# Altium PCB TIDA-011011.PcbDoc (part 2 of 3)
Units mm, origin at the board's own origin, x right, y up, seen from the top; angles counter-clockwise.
Board outline 61 x 47.5 mm, 4 copper layers (Top Layer, Layer 1, Layer 2, Bottom Layer), stack 1.787 mm thick; 171 components, 73 nets, 455 pads, 298 vias.
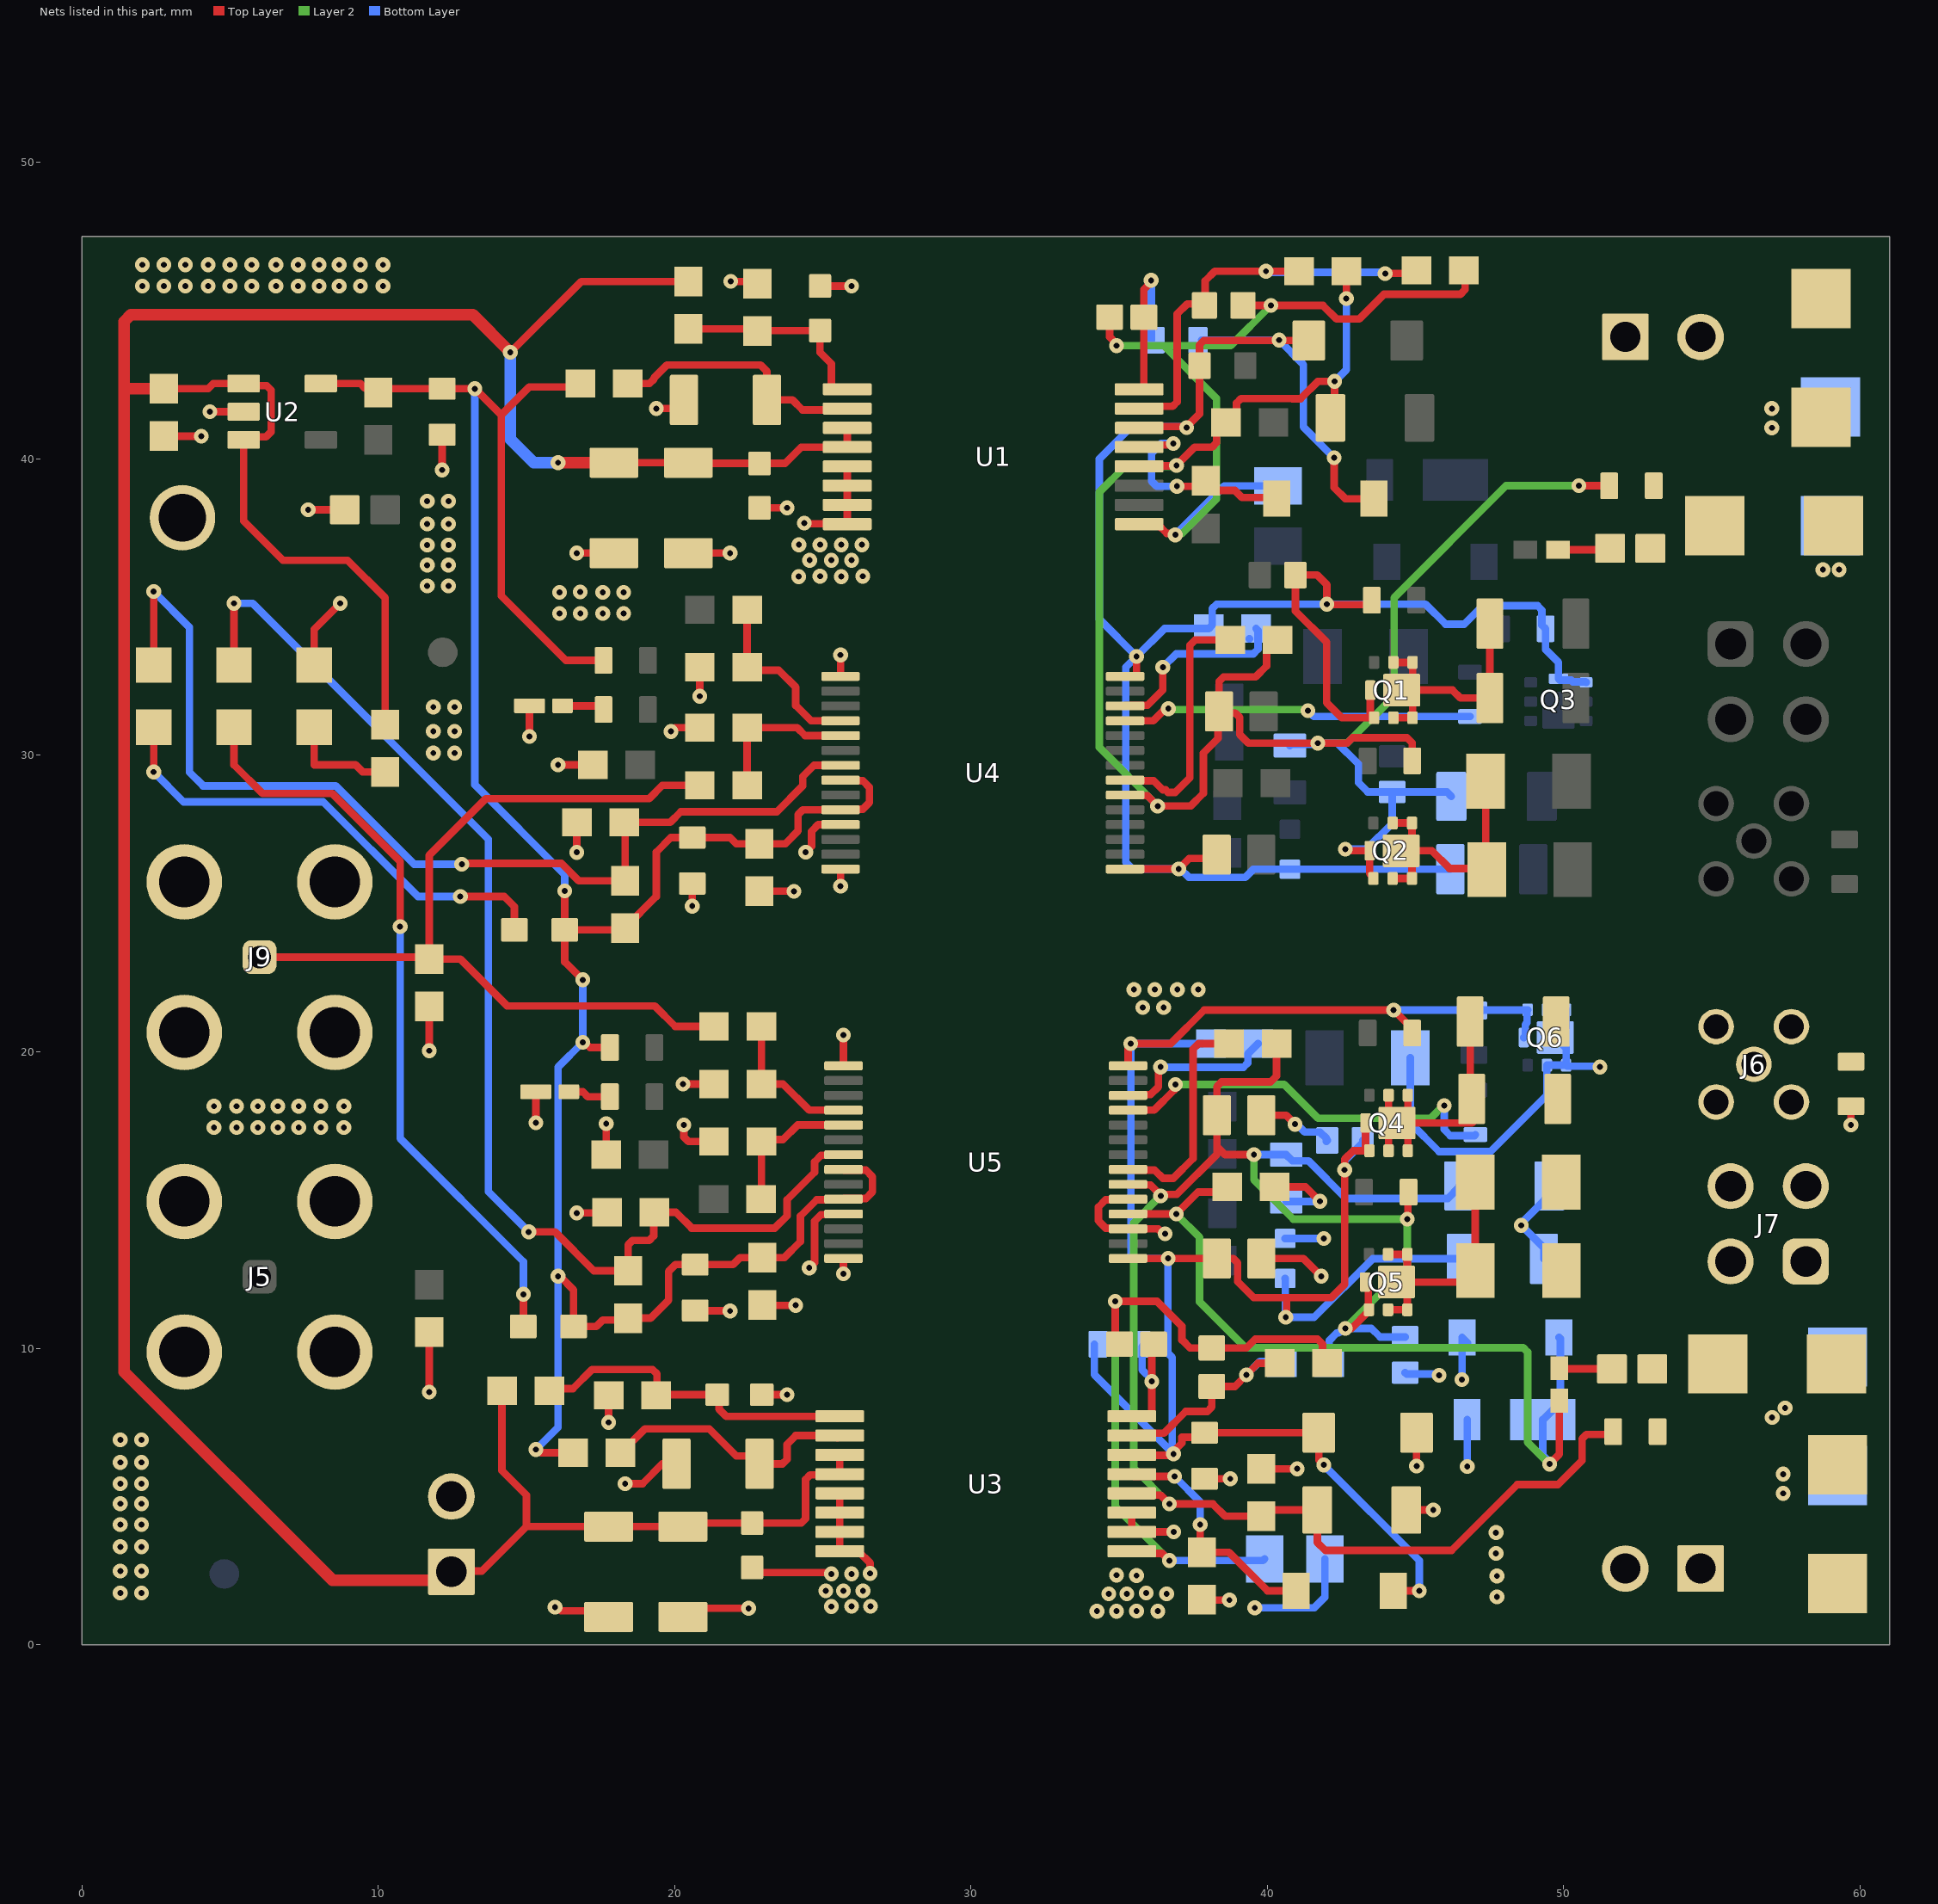
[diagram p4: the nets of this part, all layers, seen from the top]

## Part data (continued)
C40 C53: library part CMP-0122429-1, "1 µF ±10% 16V Ceramic Capacitor X7S 0603 (1608 Metric)", Digikey Part Number=490-GRM188C71C105KA12DTR-ND, Manufacturer=Murata, Mouser Part Number=81-GRM188C71C105KA2D, Operating Temperature Range="-55°C to +125°C", TempCo=22%, Temperature Characteristic=X7S, Tolerance_%=10%, ValueDisplayed=1uF
C41 C54: library part CMP-0006751-4, "CAP, CERM, 100 pF, 25 V, +/- 10%, X7R, 0603", Cap_Case=0603, Manufacturer=AVX, Supplier Part Number 1=55J3899, TempCo=X7R, Tolerance_%=10%, Value1=Unknown, Value2=25V, ValueDisplayed=100pF
C55 C56 C57 C58: library part CMP-0093594-1, "0.1 µF ±10% 50V Ceramic Capacitor X7R 0603 (1608 Metric)", Digikey Part Number=399-C0603C104K5RAC3121TR-ND, Manufacturer=KEMET, Mouser Part Number=80-C603C104K5RAC3121, Operating Temperature Range="-55°C to +125°C", TempCo=15%, Temperature Characteristic=X7R, Tolerance_%=10%, ValueDisplayed=0.1uF
D1 D2: library part CMP-0028628-2, "Diode, Schottky, 40 V, 2 A, SOD-123", Manufacturer=Rohm, Value1=2A, Value2=0.56V
D3 D4 D5: library part CMP-0002983-3, "LED, Red, SMD", Color=red, Manufacturer=OSRAM, Value1=W, Value2=1.8V
D6 D7: library part CMP-0093310-1, "Standard LEDs - SMD Green TOPLED E 1608", Color=Green, Forward Current=2mA, Manufacturer="Osram Opto", Mouser Part Number=720-KGDELLS122A4849, Operating Temperature Range="-40°C to +110°C"
D8 D9 D13 D14 D18 D19: library part CMP-0077081-2, "Diode, Ultrafast, 1200 V, 1 A, SMA", Manufacturer=STMicroelectronics, Value1=1A, Value2=1.9V
D10 D15: library part CMP-0005892-4, "Diode, Zener, 2.7 V, 300 mW, SOD-523", Manufacturer="Diodes Inc.", Power_W=300mW, Value1=0.3W
D11 D16: library part CMP-0077574-3, "Diode, Zener, 14 V, 500 mW, AEC-Q101, SOD-123", Manufacturer=Vishay-Semiconductor, Power_W=500mW, Value1=0.5W
D12 D17: library part CMP-0005417-4, "Diode, Zener, 30 V, 1 W, PowerDI123", Manufacturer="Diodes Inc.", Power_W=1W
FID1 FID2: library part CMP-0077181-1, "Fiducial mark.  There is nothing to buy or mount.", Manufacturer=N/A
J1 J4 J8: library part CMP-0092582-1, "KK 254 Breakaway Header, Right-Angle with Friction Lock, 2 Circuits, Tin (Sn) Plating", Current_A=4A, Digikey Part Number=WM19485-ND, Manufacturer=Molex, Mouser Part Number=538-22-28-1020, Operating Temperature Range=to, Voltage_V=500V
J2 J6: library part CMP-0075554-1, "Connector, MMCX 50 ohm, TH", Manufacturer=Samtec, Supplier Part Number 1=88K0549
J3 J7: library part CMP-0055713-1, "Receptacle, 2.54mm, 2x2, Gold, TH", Color=Black, Current_A=4.7A, Manufacturer=Samtec, Supplier Part Number 1=SAM1208-02-ND, Voltage_V=465V
J5 J9: library part CMP-0078588-1, "BNC JACK, 75 Ohm, Gold, R/A, TH", Manufacturer="Amphenol RF", Supplier Part Number 1=ARF2493-ND
L1 L2: library part CMP-0059575-1, "Inductor, Multilayer, Ferrite, 3.3 uH, 0.015 A, 1.55 ohm, SMD", Manufacturer="Abracon Corporation", Supplier Part Number 1=535-11599-1-ND, Value1="1.55 ohm", Value2=0.015A, ValueDisplayed=3.3uH
LBL1: library part CMP-0003625-1, "Thermal Transfer Printable Labels, 0.650\" W x 0.200\" H - 10,000 per roll", Manufacturer=Brady, Supplier Part Number 1=97C5133
Logo2: library part CMP-0074844-1
Logo3: library part CMP-0074847-1, "FCC_disclaimer"
Logo4: library part CMP-0074769-1
LOGO5: library part CMP-0074837-2, "IEC 61010-1 Hot Surface Warning", Manufacturer="Texas Instruments"
LOGO6: library part CMP-0074835-1, "IEC 61010-1 High Voltage Warning"
NT1 NT2: library part CMP-0078142-6, "Single point connection between nets.", Manufacturer=N/A
Q1 Q3 Q4 Q6: library part CMP-0120256-1, "N-Channel 40 V 8A (Ta), 19A (Tc) 2.3W (Ta), 15W (Tc) Surface Mount DFN2020MD-6", Digikey Part Number=1727-8336-1-ND, Drain To Source Breakdown Voltage=40V, Input Capacitace At Vds="582pF @ 20V", Manufacturer=Nexperia, Mouser Part Number=771-BUK6D23-40EX, Operating Temperature Range="-55°C to +175°C", Power_W=2.3W, Pulse Drain Current=76A, Typ Forward Diode Voltage=0.8V
Q2 Q5: library part CMP-0120257-1, "P-Channel 40 V 6A (Ta) 15W (Tc) Surface Mount DFN2020MD-6", Digikey Part Number=1727-BUK6D43-40PXCT-ND, Drain To Source Breakdown Voltage=-40V, Input Capacitace At Vds="1260pF @ -20V", Manufacturer=Nexperia, Mouser Part Number=771-BUK6D43-40PX, Operating Temperature Range="-55°C to +175°C", Power_W=2.3W, Pulse Drain Current=-56A, Typ Forward Diode Voltage=-0.8V
R1 R5 R8 R13: library part CMP-0024586-3, "RES, 10.0 k, 0.5%, 0.1 W, 0603", Manufacturer="Yageo America", Power_W=100mW, Supplier Part Number 1=603-RT0603DRE0710KL, TempCo="50 ppm/C", Tolerance_%=0.5%, Value2=0.1W, Value_Code=10k0, ValueDisplayed=10.0k
R2 R26 R33 R45: library part CMP-0127666-1, "1 Ohms ±0.5% 0.52W Chip Resistor 1206 (3216 Metric) Anti-Sulfur, Automotive AEC-Q200, Moisture Resistant Thin Film", Digikey Part Number=541-TNPW12061R00DEEACT-ND, Manufacturer=Vishay, Mouser Part Number=71-TNPW12061R00DEEA, Operating Temperature Range="-55°C to +175°C", Power_W=520mW, TempCo=25ppm/°C, Tolerance_%=0.5%
R3 R10 R11 R58: library part CMP-0023780-3, "RES, 15.0 k, 0.1%, 0.1 W, 0603", Manufacturer="Yageo America", Power_W=100mW, TempCo="25 ppm/C", Tolerance_%=0.1%, Value2=0.1W, Value_Code=15k0, ValueDisplayed=15.0k
R4 R12: library part CMP-0031881-1, "51 kOhms ±0.5% 0.1W, 1/10W Chip Resistor 0603 (1608 Metric) Automotive AEC-Q200 Thin Film", Digikey Part Number=P123905CT-ND, Manufacturer=Panasonic, Mouser Part Number=667-ERA-3AED513V, Operating Temperature Range="-55°C to +155°C", Power_W=100mW, TempCo=25ppm/°C, Tolerance_%=0.5%
R6 R14: library part CMP-0025064-3, "RES, 2.40 k, 0.5%, 0.1 W, 0603", Manufacturer="Yageo America", Power_W=100mW, TempCo="50 ppm/C", Tolerance_%=0.5%, Value2=0.1W, Value_Code=2k40, ValueDisplayed=2.40k
R7: library part CMP-0023508-3, "RES, 30.0 k, 0.1%, 0.1 W, 0603", Manufacturer="Susumu Co Ltd", Power_W=100mW, Supplier Part Number 1=RG16P30.0KBCT-ND, TempCo="25 ppm/C", Tolerance_%=0.1%, Value2=0.1W, Value_Code=30k0, ValueDisplayed=30.0k
R9: library part CMP-0126340-1, "10 kOhms ±0.01% 0.125W, 1/8W Chip Resistor 0603 (1608 Metric) Anti-Sulfur, Moisture Resistant Thin Film", Digikey Part Number=716-P2TC0603D1002LNTACT-ND, Manufacturer=Vishay, Mouser Part Number=72-P2TC0603D1002LNTA, Operating Temperature Range="-55°C to +155°C", Power_W=125mW, TempCo=2ppm/°C, Tolerance_%=0.01%
R15 R16 R25 R31 R37 R38 R39 R44 R50 R54 R55 R56: library part CMP-0125815-1, "10 kOhms ±1% 0.1W, 1/10W Chip Resistor 0603 (1608 Metric) Anti-Sulfur Thick Film", Digikey Part Number=732-560112116005CT-ND, Manufacturer="Wurth Electronics", Mouser Part Number=710-560112116005, Operating Temperature Range="-55°C to +155°C", Power_W=100mW, TempCo=100ppm/°C, Tolerance_%=1%
R17: library part CMP-0022685-3, "RES, 12.0 k, 1%, 0.1 W, 0603", Manufacturer=Panasonic, Power_W=100mW, Supplier Part Number 1=P12.0KHCT-ND, TempCo="100 ppm/C", Tolerance_%=1%, Value2=0.1W, Value_Code=12k0, ValueDisplayed=12.0k
R18 R19: library part CMP-0122747-1, "8 kOhms ±0.1% 0.1W, 1/10W Chip Resistor 0603 (1608 Metric) Thin Film", Digikey Part Number=13-RT0603BRE078KLCT-ND, Manufacturer=Yageo, Mouser Part Number=603-RT0603BRE078KL, Operating Temperature Range="-55°C to +155°C", Power_W=100mW, TempCo=50ppm/°C, Tolerance_%=0.1%
R20 R21: library part CMP-0125827-1, "24.9 kOhms ±1% 0.1W, 1/10W Chip Resistor 0603 (1608 Metric) Anti-Sulfur Thick Film", Digikey Part Number=732-560112116140CT-ND, Manufacturer="Wurth Electronics", Mouser Part Number=710-560112116140, Operating Temperature Range="-55°C to +155°C", Power_W=100mW, TempCo=100ppm/°C, Tolerance_%=1%
R22 R23 R29 R32 R41 R42 R48 R51: library part CMP-0023691-3, "RES, 120, 0.1%, 0.1 W, 0603", Manufacturer="Yageo America", Power_W=100mW, TempCo="25 ppm/C", Tolerance_%=0.1%, Value2=0.1W, Value_Code=120R, ValueDisplayed=120
R24 R43: library part CMP-0016910-3, "RES, 32.4, 1%, 0.25 W, AEC-Q200 Grade 0, 1206", Manufacturer=Vishay-Dale, Power_W=250mW, Supplier Part Number 1=541-32.4FCT-ND, TempCo="100 ppm/C", Tolerance_%=1%, Value2=0.25W, Value_Code=32R4, ValueDisplayed=32.4
R27 R30 R46 R49: library part CMP-0018677-3, "RES, 3.3, 5%, 0.25 W, AEC-Q200 Grade 0, 1206", Manufacturer=Vishay-Dale, Power_W=250mW, Supplier Part Number 1=541-3.3ECT-ND, TempCo="200 ppm/C", Tolerance_%=5%, Value2=0.25W, Value_Code=3R30, ValueDisplayed=3.3
R28 R47: library part CMP-0024852-2, "RES, 1.00 k, 0.5%, 0.1 W, 0603", Manufacturer="Yageo America", Power_W=100mW, TempCo="50 ppm/C", Tolerance_%=0.5%, Value2=0.1W, Value_Code=1k00, ValueDisplayed=1.00k
R34 R53: library part CMP-0094841-1, "10 Ohms ±1% 0.25W, 1/4W Chip Resistor 0603 (1608 Metric) Automotive AEC-Q200, Pulse Withstanding Thick Film", Digikey Part Number=RHM10.0ADCT-ND, Manufacturer=ROHM, Mouser Part Number=755-ESR03EZPF10R0, Operating Temperature Range="-55°C to +155°C", Power_W=250mW, TempCo=100ppm/°C, Tolerance_%=1%
R35 R36: library part CMP-0025433-3, "RES, 5.05 k, 0.5%, 0.1 W, 0603", Manufacturer="Yageo America", Power_W=100mW, TempCo="50 ppm/C", Tolerance_%=0.5%, Value2=0.1W, Value_Code=5k05, ValueDisplayed=5.05k
R40 R57: library part CMP-0096427-1, "1 kOhms ±0.01% 0.125W, 1/8W Chip Resistor 0603 (1608 Metric) Anti-Sulfur, Moisture Resistant Thin Film", Digikey Part Number=716-P2TC0603D1001LNTACT-ND, Manufacturer=Vishay, Mouser Part Number=72-P2TC0603D1001LNTA, Operating Temperature Range="-55°C to +155°C", Power_W=125mW, TempCo=2ppm/°C, Tolerance_%=0.01%
TP2: library part CMP-0055148-2, "Test Point, Multipurpose, Black, TH", Color=Black, Manufacturer="Keystone Electronics", Supplier Part Number 1=36-5011-ND
U1 U3: library part CMP-0126653-2, "Automotive 2.0W, 12V VIN, High-Density, > 5kVRMS, Isolated DC/DC Module", Manufacturer="Texas Instruments", Max Supply Voltage=20V, Min Supply Voltage=5.5V, Operating Temperature Range="-40°C to +150°C", Output Voltage=-2-8/12-18V
U2: library part CMP-0096923-1, "Linear Voltage Regulator IC  1 Output  200mA SOT-23-5", Digikey Part Number=296-TPS7A2450DBVRCT-ND, Dropout Voltage=160mV, Manufacturer="Texas Instruments", Max Supply Voltage=18V, Min Supply Voltage=2.4V, Mouser Part Number=595-TPS7A2450DBVR, Nominal Supply Current=2-15uA, Operating Temperature Range="-40°C to +125°C", Output Voltage=5V
U4 U5: library part CMP-0128293-1, "Single Channel Isolated Pre-Driver for SiC/IGBT with Active Protection", Manufacturer="Texas Instruments", Max Supply Voltage=28V, Min Supply Voltage=3V, Operating Temperature Range="-40°C to +125°C"
ZZ1: library part CMP-0003616-3
ZZ2: library part CMP-0077236-1
ZZ3: library part CMP-0077237-1
ZZ4: library part CMP-0077238-1

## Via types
v1: diameter 0.5, hole 0.2, Top Layer to Bottom Layer, tented both sides, 298 vias

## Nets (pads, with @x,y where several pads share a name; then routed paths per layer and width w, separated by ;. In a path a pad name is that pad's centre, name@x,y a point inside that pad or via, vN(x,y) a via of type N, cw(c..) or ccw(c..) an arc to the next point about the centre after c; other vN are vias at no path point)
+5V: C12.2 C29.2 C30.2 C42.2 C43.2 R1.2 R7.2 R8.2 R15.2 R16.2 R18.2 R19.2 R35.2 R36.2 U2.5 U4.8 U4.10 U5.8 U5.10 | length 91.7
  Top Layer w0.254: U2.5@8.063,42.543 9.4,42.543 9.554,42.389 10.183,42.389 10.247,42.325 10.289,42.368 C12.2@12.16,42.368 v1(13.265,42.368) 14.151,41.481 ; v1@15.498,6.476 R8.2@16.571,6.476 ; v1(16.07,12.432) 16.135,12.432 16.595,11.972 R19.2@16.595,10.736 17.361,10.736 17.578,10.953 18.369,10.953 R36.2@18.433,11.016 19.189,11.016 19.797,11.625 19.797,12.593 20.03,12.826 C42.2@20.697,12.826 21.972,12.826 22.206,13.059 C43.2@22.962,13.059 23.706,13.059 24.248,13.601 24.248,14.458 24.799,15.009 25.677,15.009 U5.10@25.7,15.032 25.723,15.055 26.456,15.055 26.677,15.275 26.677,15.788 26.456,16.009 25.723,16.009 U5.8@25.7,16.032 ; v1(16.296,25.426) R18.2@16.296,24.116 ; R1.2@16.821,42.543 16.705,42.427 15.096,42.427 14.151,41.481 ; v1(16.904,20.323) 16.97,20.323 17.149,20.144 R15.2@17.819,20.144 ; v1(16.904,22.429) 16.296,23.037 R18.2@16.296,24.116 ; R16.2@17.604,33.204 16.332,33.204 14.151,35.385 14.151,41.481 ; U4.8@25.6,29.166 25.623,29.143 26.356,29.143 26.577,28.922 26.577,28.409 26.356,28.189 25.623,28.189 U4.10@25.6,28.166 24.328,28.166 24.169,28.007 24.169,27.45 23.737,27.018 C30.2@22.862,27.018 22.084,27.018 21.875,27.227 C29.2@20.597,27.227 19.876,27.227 19.383,26.734 19.383,25.243 18.333,24.192 R35.2@18.333,24.167 18.281,24.116 R18.2@16.296,24.116
  Bottom Layer w0.254: v1(13.265,42.368) 13.265,29.008 16.296,25.977 v1(16.296,25.426) ; v1(15.321,6.586) 16.07,7.334 v1(16.07,12.432) 16.07,19.489 v1(16.904,20.323) v1(16.904,22.429)
+12V: C3.2 C4.2 C9.2 C13.1 C16.2 C17.2 C22.2 J1.1 R3.2 R11.2 R17.2 U1.3 U1.4 U2.1 U2.3 U3.3 U3.4 | length 126.9
  Top Layer w0.254: C13.1@2.774,42.368 4.263,42.368 4.438,42.543 U2.1@5.463,42.543 5.538,42.468 6.24,42.468 6.388,42.319 6.388,40.915 6.215,40.742 5.562,40.742 U2.3@5.463,40.643 5.463,37.908 6.788,36.583 8.966,36.583 10.233,35.316 R17.2@10.233,31.041 ; J1.1@12.471,2.464 12.494,2.486 13.5,2.486 15.001,3.988 ; R11.2@14.178,8.565 14.178,5.874 15.001,5.05 15.001,3.988 ; v1(14.459,43.593) 16.852,45.986 R3.2@20.466,45.986 ; C4.2@17.957,39.873 C3.2@20.466,39.873 20.49,39.849 C9.2@22.867,39.849 23.724,39.849 24.274,40.399 U1.4@25.825,40.399 U1.3@25.825,41.049 ; U3.3@25.575,6.407 U3.4@25.575,5.757 25.546,5.728 24.572,5.728 24.423,5.579 24.423,4.258 24.274,4.109 C22.2@22.617,4.109 20.405,4.109 C16.2@20.283,3.988 C17.2@17.775,3.988 15.001,3.988
  Top Layer w0.4: C13.1@2.774,42.368 1.427,42.368 ; J1.1@12.471,2.464 12.185,2.178 8.457,2.178 1.427,9.208 1.427,42.368 ; v1(14.459,43.593) 13.185,44.868 1.661,44.868 1.427,44.633 1.427,42.368 ; v1(16.07,39.873) C4.2@17.957,39.873
  Bottom Layer w0.4: v1(14.459,43.593) 14.459,40.666 15.253,39.873 v1(16.07,39.873)
+18V_BOT: C14.1 C15.2 C45.1 C48.2 C49.2 C50.2 C57.2 Q5.4 Q5.8 R10.2 R44.2 R56.2 U3.12 U5.20 | length 67.3
  Top Layer w0.254: U5.20@35.3,15.532 35.323,15.509 36.056,15.509 36.401,15.164 v1(36.401,15.143) 36.448,15.19 36.942,15.19 38.297,16.545 38.297,16.81 ; U3.12@35.425,5.107 35.481,5.05 36.401,5.05 v1(36.698,4.753) ; v1@36.631,4.753 38.159,4.753 38.577,4.336 C14.1@39.797,4.336 40.007,4.546 C15.2@41.685,4.546 41.685,3.454 41.954,3.185 46.217,3.185 48.434,5.402 49.804,5.402 50.617,6.215 50.617,6.946 50.766,7.095 R56.2@51.573,7.095 ; v1(39.546,16.53) 38.577,16.53 38.297,16.81 ; C45.1@40.312,20.274 40.312,19.191 40.104,18.983 38.446,18.983 38.297,18.834 C49.2@38.297,17.86 38.297,16.81 ; v1(42.627,10.673) 42.837,10.673 43.424,11.259 Q5.4@43.424,11.299 43.407,11.316 43.407,11.971 43.299,12.079 Q5.8@43.299,12.234 ; v1(44.721,14.355) 44.743,14.377 44.743,15.246 R44.2@44.764,15.268
  Layer 2 w0.254: v1(36.401,15.143) 35.495,14.237 35.495,5.956 v1(36.698,4.753) ; v1(39.546,16.53) 39.546,15.683 40.873,14.355 v1(44.721,14.355) 44.721,12.767 v1(42.627,10.673)
  Bottom Layer w0.254: v1(39.546,16.53) C50.2@40.637,16.53 40.845,16.322 41.39,16.322 42.657,15.055 46.091,15.055 46.472,15.436 C48.2@46.472,15.477 ; R10.2@42.086,9.505 42.086,10.262 42.342,10.518 42.405,10.518 42.56,10.673 v1(42.627,10.673) 43.511,10.673 43.805,10.379 C57.2@44.651,10.379
+18V_TOP: C1.1 C2.2 C26.1 C35.2 C36.2 C37.2 C55.2 Q2.4 Q2.8 R25.2 R39.2 R58.2 U1.12 U4.20 | length 72.2
  Top Layer w0.254: U4.20@35.2,28.666 35.223,28.643 35.956,28.643 v1@36.3,28.3 ; U1.12@35.675,39.749 35.69,39.763 36.921,39.763 v1(36.936,39.778) ; v1@36.302,28.297 37.418,28.297 37.842,28.722 37.842,30.078 38.338,30.574 38.338,31.446 C36.2@38.373,31.481 ; v1(36.936,39.778) 36.936,39.791 37.544,40.399 38.137,40.399 38.285,40.547 38.285,40.909 C1.1@38.608,41.231 38.612,41.231 38.96,41.579 38.96,41.884 39.109,42.033 40.843,42.033 40.846,42.031 41.119,42.031 41.705,42.617 v1@42.128,42.617 ; C26.1@40.346,33.896 40.321,33.896 39.973,33.548 39.973,33.017 39.601,32.644 38.522,32.644 38.373,32.495 C36.2@38.373,31.481 ; C2.2@42.128,41.384 42.27,41.526 v1(42.27,42.617) ; v1(42.628,26.839) 42.684,26.783 Q2.8@43.453,26.783 43.453,26.013 43.578,25.888 Q2.4@43.578,25.848 ; v1(42.664,45.406) R58.2@42.664,46.33 ; R25.2@44.888,29.816 44.888,30.421 44.715,30.593 42.871,30.593 42.69,30.412 v1(41.702,30.412) 39.361,30.412 39.071,30.701 39.071,31.282 38.923,31.431 38.423,31.431 C36.2@38.373,31.481 ; v1(50.509,39.099) 51.528,39.099 R39.2@51.536,39.091
  Layer 2 w0.254: v1(36.3,28.287) 36.3,28.3 34.334,30.265 34.334,38.883 35.2,39.749 36.906,39.749 v1(36.936,39.778) ; v1(41.702,30.412) 42.69,30.412 44.275,31.997 44.275,35.319 48.055,39.099 v1(50.509,39.099)
  Bottom Layer w0.254: C37.2@40.762,30.331 40.802,30.371 41.661,30.371 v1(41.702,30.412) 42.366,30.412 43.071,29.707 43.071,29.083 43.388,28.766 C55.2@44.138,28.766 ; v1(42.27,42.617) 42.664,43.011 v1(42.664,45.406) ; v1(42.628,26.839) 43.349,26.839 44.213,27.702 C55.2@44.213,28.766 46.058,28.766 C35.2@46.208,28.616
-5V_BOT: C23.1 C24.1 C44.1 C51.1 C52.1 C53.1 C58.1 D2.2 Q4.4 Q4.8 Q6.4 Q6.8 R12.1 R54.1 R55.1 U3.14 U5.15 U5.28 | length 77.6
  Top Layer w0.254: U5.15@35.3,13.032 v1(36.649,13.032) C52.1@38.297,13.032 38.846,13.032 38.995,12.883 38.995,12.252 39.538,11.709 40.681,11.709 ; U5.28@35.3,19.532 v1@35.3,20.12 ; v1(35.394,20.281) 36.743,20.281 37.873,21.411 v1(44.261,21.411) 44.888,20.784 R54.1@44.888,20.634 ; U3.14@35.425,6.407 35.444,6.388 36.726,6.388 36.745,6.369 36.745,6.435 37.119,6.81 37.119,7.003 37.734,7.003 C23.1@37.882,7.151 41.732,7.151 C24.1@41.735,7.154 41.735,6.234 v1(41.902,6.067) ; v1(40.621,11.05) 40.653,11.082 40.653,11.681 40.681,11.709 ; Q4.8@43.314,17.601 43.314,16.831 43.439,16.706 Q4.4@43.439,16.666 42.896,16.666 42.607,16.377 42.607,12.158 42.158,11.709 40.681,11.709 ; D2.2@44.242,1.819 v1(45.128,1.819)
  Bottom Layer w0.254: R12.1@34.162,10.14 34.162,9.113 v1@36.788,6.486 ; v1(36.835,6.439) v1@36.788,6.486 ; C44.1@37.793,20.281 v1(35.394,20.281) 35.394,13.188 35.55,13.032 v1(36.649,13.032) 36.649,9.833 36.788,9.693 v1@36.788,6.486 ; C53.1@40.597,12.357 40.609,12.345 40.609,11.062 v1(40.621,11.05) 41.581,11.05 43.55,13.019 C51.1@46.528,13.019 ; v1(41.902,6.067) 45.128,2.841 v1(45.128,1.819) ; v1(42.607,16.018) 42.607,16.321 43.22,16.934 C58.1@43.22,17.009 ; v1(44.261,21.411) R55.1@46.954,21.411 ; R55.1@46.984,21.406 Q6.4@48.768,21.406 ; Q6.8@48.655,20.483 48.703,20.531 48.703,20.919 48.763,20.979 48.763,21.401 Q6.4@48.768,21.406 ; Q6.4@48.78,21.418 Q6.4@48.768,21.406
-5V_TOP: C10.1 C11.1 C25.1 C38.1 C39.1 C40.1 C56.1 D1.2 Q1.4 Q1.8 Q3.4 Q3.8 R4.1 R37.1 R38.1 U1.14 U4.15 U4.28 | length 81.4
  Top Layer w0.254: U4.15@35.2,26.166 v1(37.009,26.166) 37.364,26.521 38.158,26.521 C39.1@38.29,26.653 C39.1@38.304,26.64 ; U4.28@35.2,32.666 35.564,32.666 35.587,32.689 v1(35.587,33.338) ; U1.14@35.675,41.049 35.719,41.093 37.235,41.093 v1(37.273,41.056) 37.273,41.075 37.709,41.512 C10.1@37.709,43.146 37.709,43.843 37.858,43.992 C11.1@41.401,43.992 ; v1(42.251,40.041) 42.251,39.04 42.634,38.657 D1.2@43.593,38.657 ; Q1.8@43.427,32.273 43.475,32.225 Q1.8@43.475,32.201 43.475,31.431 43.6,31.306 43.56,31.266 42.509,31.266 41.997,31.779 41.997,33.819 40.946,34.869 C56.1@40.946,36.084 41.681,36.084 42.01,35.755 v1(42.01,35.1) 42.025,35.085 43.375,35.085 R37.1@43.525,35.235
  Bottom Layer w0.254: v1(37.273,41.056) 37.235,41.093 35.42,41.093 34.334,40.007 34.334,34.591 v1(35.587,33.338) ; R4.1@37.784,44.008 v1(40.394,44.008) 41.218,43.185 41.218,41.074 v1(42.251,40.041) ; C38.1@46.173,26.158 C40.1@40.762,26.158 39.529,26.158 39.26,25.889 37.353,25.889 37.075,26.166 v1(37.009,26.166) 35.451,26.166 35.223,26.394 35.223,32.974 v1(35.587,33.338) ; Q3.4@50.755,32.463 50.738,32.48 50.306,32.48 50.246,32.54 49.868,32.54 Q3.8@49.82,32.588 49.82,33.139 49.387,33.572 R38.1@49.387,34.272 49.264,34.394 49.264,34.9 49.115,35.049 47.264,35.049 46.638,34.423 46.014,34.423 45.337,35.1 v1(42.01,35.1) 38.291,35.1 38.142,34.951 38.142,34.396 C25.1@38.023,34.277 36.526,34.277 v1(35.587,33.338)
BF_OFF_BOT: Q4.1 Q4.2 Q4.5 Q4.6 Q4.7 R33.1 R45.1 | length 9.5
  Top Layer w0.254: Q4.5@44.089,16.666 Q4.2@44.089,18.536 ; Q4.6@44.739,16.666 44.739,17.236 Q4.7@44.374,17.601 ; Q4.1@44.739,18.536 44.739,17.966 Q4.7@44.374,17.601 ; R45.1@46.845,21.018 46.845,18.461 R33.1@46.896,18.409 ; R33.1@47.103,17.802 46.901,17.601 Q4.7@44.374,17.601
BF_OFF_TOP: Q1.1 Q1.2 Q1.5 Q1.6 Q1.7 R2.1 R26.1 | length 9.1
  Top Layer w0.254: Q1.5@44.25,31.266 Q1.6@44.9,31.266 44.9,31.836 Q1.7@44.535,32.201 ; Q1.2@44.25,33.136 Q1.1@44.9,33.136 44.9,32.566 Q1.7@44.535,32.201 ; R2.1@47.51,34.443 R26.1@47.51,31.934 46.513,31.934 46.246,32.201 Q1.7@44.535,32.201
BF_ON_BOT: Q5.1 Q5.2 Q5.5 Q5.6 Q5.7 R46.1 R49.1 | length 9.3
  Top Layer w0.254: Q5.5@44.074,11.299 Q5.6@44.724,11.299 44.724,11.869 Q5.7@44.359,12.234 ; Q5.2@44.074,13.169 Q5.1@44.724,13.169 44.724,12.599 Q5.7@44.359,12.234 ; R49.1@47.014,12.633 R46.1@47.014,15.602 ; R49.1@47.022,12.624 46.633,12.234 Q5.7@44.359,12.234
BF_ON_TOP: Q2.1 Q2.2 Q2.5 Q2.6 Q2.7 R27.1 R30.1 | length 9.5
  Top Layer w0.254: Q2.5@44.228,25.848 Q2.6@44.878,25.848 44.878,26.418 Q2.7@44.513,26.783 ; Q2.2@44.228,27.718 Q2.1@44.878,27.718 44.878,27.148 Q2.7@44.513,26.783 ; R27.1@47.365,29.127 47.365,26.186 46.146,26.186 45.549,26.783 Q2.7@44.513,26.783
BOT-PWM: J9.1 R23.1 R28.2 R41.1 | length 29.9
  Top Layer w0.254: J9.1@6,23.194 11.656,23.194 R28.2@11.721,23.129 ; R23.1@20.85,28.99 19.59,28.99 19.143,28.543 13.636,28.543 11.721,26.628 R28.2@11.721,23.129 ; R41.1@21.329,20.856 20.023,20.856 19.331,21.549 14.352,21.549 12.772,23.129 R28.2@11.721,23.129
BOT_Gate: J6.1 J7.2 J7.4 Q6.1 Q6.2 Q6.5 Q6.6 Q6.7 R33.2 R43.2 R45.2 R46.2 R49.2 R50.2 | length 14.1
  Top Layer w0.254: R45.2@49.745,21.018 R45.2@49.77,20.993 ; R33.2@49.77,18.435 R33.2@49.796,18.409 ; R49.2@49.914,12.633 R49.2@49.922,12.624
  Bottom Layer w0.254: R43.2@44.825,19.799 44.825,17.601 45.792,16.634 47.528,16.634 49.43,18.536 Q6.2@49.43,19.548 Q6.1@50.08,19.548 ; Q6.5@49.43,21.418 49.43,20.768 Q6.7@49.715,20.483 ; Q6.6@50.08,21.418 50.08,20.848 Q6.7@49.715,20.483 ; v1(51.224,19.489) 51.195,19.519 50.11,19.519 Q6.1@50.08,19.548 ; Q6.7@49.715,20.483 50.08,20.118 Q6.1@50.08,19.548
BOT_OC: C54.1 D15.1 D16.1 D17.1 U5.18 | length 29.8
  Top Layer w0.254: U5.18@35.3,14.532 v1(36.926,14.532) 37.668,15.274 38.473,15.274 C54.1@38.643,15.445 ; v1(49.52,6.096) 49.853,6.429 D15.1@49.853,8.234
  Layer 2 w0.254: v1(36.926,14.532) 37.715,13.742 37.715,11.562 39.256,10.022 48.631,10.022 48.78,9.873 48.78,6.836 v1(49.52,6.096)
  Bottom Layer w0.254: v1(49.52,6.096) 49.52,6.163 49.294,6.388 D17.1@49.294,7.598 49.31,7.598 49.883,8.171 49.883,10.326 D16.1@49.842,10.367
BOT_Source: C14.2 C15.1 C23.2 C24.2 C48.1 C49.1 C50.1 C51.2 C52.2 C53.2 C54.2 C57.1 C58.2 D16.2 D17.2 J6.2 J6.3 J6.4 J6.5 J7.1 J7.3 L2.1 NT2.2 R50.1 U3.10 U3.11 U5.17 U5.19 | length 32.4
  Top Layer w0.254: U5.19@35.3,15.032 35.277,15.009 34.544,15.009 34.3,14.765 34.3,14.307 34.323,14.284 34.323,14.275 34.544,14.055 35.277,14.055 U5.17@35.3,14.032 36.315,14.032 36.482,13.865 v1(36.548,13.865) ; U3.11@35.425,4.457 U3.10@35.425,3.807 v1(36.84,3.807) ; L2.1@37.793,1.521 37.806,1.509 v1(38.72,1.509) ; C23.2@37.882,5.601 v1(38.748,5.601) ; C14.2@39.797,5.936 v1(41.009,5.936) ; C49.1@39.797,17.86 40.634,17.86 v1(40.936,17.558) ; C52.2@39.814,13.048 C52.2@39.797,13.032 41.219,13.032 41.814,12.436 v1(41.814,12.432) ; C54.2@40.243,15.445 41.286,15.445 v1(41.772,14.959) ; C15.1@44.685,4.546 v1(45.599,4.546) ; v1(45.035,6.026) C24.2@45.035,7.154 ; v1(59.688,17.531) R50.1@59.688,18.166
  Bottom Layer w0.254: v1(39.575,1.248) 41.583,1.248 41.941,1.606 NT2.2@41.941,2.899 ; C53.2@40.597,13.707 v1(41.902,13.707) ; C50.1@40.637,14.95 40.641,14.955 41.768,14.955 v1(41.772,14.959) ; v1(40.936,17.558) 41.002,17.558 41.264,17.296 41.772,17.296 41.995,17.073 41.995,16.984 C58.2@42.02,17.009 ; C57.1@44.651,9.179 44.696,9.134 45.748,9.134 v1(45.792,9.089) ; v1(46.567,8.944) D16.2@46.567,10.367 46.757,10.177 D16.2@46.672,10.091 ; v1(46.744,6.011) D17.2@46.744,7.598 ; v1(48.562,14.145) 48.577,14.144 48.979,13.742 48.98,13.742 49.328,13.394 C51.2@49.328,13.019 ; v1(48.562,14.145) 48.562,14.202 49.52,15.16 C48.1@49.52,15.477
  other v1: 34.25,1.133 34.912,1.133 35.587,1.135 36.301,1.133 47.745,1.616 34.649,1.716 35.258,1.721 36.601,1.715 35.916,1.744 47.745,2.321 34.912,2.351 35.587,2.335 47.714,3.079 47.714,3.784 35.794,21.494 36.499,21.494 35.5,22.1 36.205,22.1 36.963,22.1 37.668,22.1
FLT_BOT: C32.1 D4.2 R36.1 U5.7 | length 42.5
  Top Layer w0.254: D4.2@5.135,33.046 v1(5.135,35.127) ; v1(15.08,13.926) 15.967,13.926 17.277,12.616 R36.1@18.433,12.616 18.433,13.492 18.581,13.641 19.146,13.641 19.295,13.79 19.295,14.565 C32.1@19.319,14.59 20.043,14.59 20.577,14.055 23.385,14.055 23.794,14.464 23.794,15.009 24.723,15.937 24.723,16.288 24.944,16.509 25.677,16.509 U5.7@25.7,16.532
  Bottom Layer w0.254: v1(5.135,35.127) 5.766,35.127 13.722,27.171 13.722,15.284 v1(15.08,13.926)
FLT_TOP: C31.1 D3.2 R35.1 U4.7 | length 35.6
  Top Layer w0.254: D3.2@2.427,33.046 v1(2.427,35.527) ; v1(12.822,26.331) 12.846,26.355 16.182,26.355 16.77,25.767 R35.1@18.333,25.767 18.333,27.71 C31.1@18.302,27.741 19.852,27.741 20.212,28.1 23.453,28.1 24.325,28.972 24.325,29.289 24.702,29.666 U4.7@25.6,29.666
  Bottom Layer w0.254: v1(2.427,35.527) 3.634,34.32 3.634,29.433 4.095,28.972 8.568,28.972 11.209,26.331 v1(12.822,26.331)
GND: C3.1 C4.1 C5.1 C8.1 C9.1 C12.1 C13.2 C16.1 C17.1 C18.1 C21.1 C22.1 C27.2 C28.2 C29.1 C30.1 C31.2 C32.2 C33.2 C34.2 C42.1 C43.1 C46.2 C47.2 D5.2 D6.1 D7.1 J1.2 J5.2 J5.3 J5.4 J5.5 J9.2 J9.3 J9.4 J9.5 R5.1 R9.1 R13.1 R28.1 R47.1 TP2.1 U1.5 U1.6 U1.7 U1.8 U2.2 U3.5 U3.6 U3.7 U3.8 U4.1 U4.11 U4.14 U5.1 U5.11 U5.14 | length 58.1
  Top Layer w0.254: C13.2@2.774,40.768 v1(4.031,40.768) ; v1(4.325,41.593) U2.2@5.463,41.593 ; v1(7.638,38.284) R9.1@8.874,38.284 ; D5.2@7.843,33.046 7.843,34.253 v1(8.718,35.127) ; v1(11.721,8.523) R47.1@11.721,10.548 ; v1(11.721,20.038) R28.1@11.721,21.529 ; v1(12.16,39.627) C12.1@12.16,40.818 ; v1(15.106,30.634) D7.1@15.106,31.671 ; v1(15.321,17.607) D6.1@15.321,18.655 ; v1(15.967,1.266) 16.034,1.266 16.157,1.143 C17.1@17.876,1.143 ; v1(16.07,29.683) C34.2@17.245,29.683 ; v1(16.702,14.565) 17.694,14.565 C32.2@17.719,14.59 ; v1(16.702,26.729) C31.2@16.702,27.741 ; v1(16.702,36.825) C4.1@17.957,36.825 ; C33.2@17.695,16.532 v1(17.695,17.575) ; v1(17.775,7.5) 17.775,8.408 R13.1@17.783,8.415 ; v1(18.333,5.435) 18.92,5.435 19.59,6.104 C18.1@20.067,6.104 ; v1(19.383,41.699) 20.026,41.699 C5.1@20.317,41.989 ; v1(19.876,30.807) 20.002,30.933 C27.2@20.85,30.933 ; C16.1@20.283,0.94 20.573,1.229 v1(22.498,1.229) ; v1(20.286,18.916) C47.2@21.329,18.916 ; v1(20.317,17.532) 20.317,17.123 20.466,16.974 C46.2@21.329,16.975 ; C3.1@20.466,36.825 v1(21.875,36.825) ; v1(20.597,24.916) C29.1@20.597,25.677 ; C42.1@20.697,11.276 20.705,11.268 21.867,11.268 v1(21.875,11.259) ; v1(20.85,31.996) C28.2@20.85,32.975 ; v1(21.893,45.986) 22.718,45.986 R5.1@22.794,45.91 ; C22.1@22.617,2.609 22.789,2.437 25.243,2.437 v1(25.29,2.39) ; C30.1@22.862,25.418 v1(24.025,25.418) ; C9.1@22.867,38.349 v1(23.794,38.349) ; C21.1@22.942,8.437 v1(23.794,8.437) ; C43.1@22.962,11.459 22.971,11.45 v1(24.089,11.45) ; v1(24.377,37.831) 24.393,37.815 25.809,37.815 U1.8@25.825,37.799 U1.7@25.825,38.449 U1.6@25.825,39.099 U1.5@25.825,39.749 ; v1(24.425,26.734) 24.623,26.932 24.623,27.438 24.851,27.666 U4.11@25.6,27.666 ; v1(24.543,12.712) 24.723,12.892 24.723,14.288 24.944,14.509 25.677,14.509 U5.11@25.7,14.532 U5.11@25.723,14.555 ; C8.1@24.909,45.832 v1(25.975,45.832) ; U3.5@25.575,5.107 U3.6@25.575,4.457 U3.7@25.575,3.807 U3.8@25.575,3.157 26.195,3.157 26.6,2.752 v1(26.6,2.406) ; v1(25.6,25.591) U4.14@25.6,26.166 ; U4.1@25.6,32.666 v1(25.6,33.388) ; v1@25.647,25.477 25.647,25.581 25.657,25.591 v1@25.647,25.601 ; U4.14@25.647,26.179 U4.14@25.657,26.189 ; U5.1@25.657,19.509 U5.1@25.7,19.552 ; v1(25.7,12.515) U5.14@25.7,13.032 ; U5.1@25.7,19.532 U5.1@25.7,19.552 ; v1(25.7,20.571) v1@25.7,20.528 ; v1@25.7,20.614 25.657,20.571 v1@25.7,20.528 ; U5.1@25.7,19.552 v1@25.7,20.528
  Bottom Layer w0.254: v1@25.062,1.782 v1(25.099,1.819)
  other v1: 25.29,1.291 25.975,1.299 26.61,1.299 1.3,1.751 2.015,1.751 25.7,1.819 26.356,1.819 25.975,2.39 1.3,2.486 2.015,2.486 1.3,3.305 2.015,3.305 1.3,4.055 2.015,4.055 1.3,4.76 2.015,4.76 1.3,5.435 2.015,5.435 1.3,6.151 2.015,6.151 1.3,6.916 2.015,6.916 4.46,17.45 5.225,17.45 5.941,17.45 6.616,17.45 7.321,17.45 8.063,17.45 8.843,17.45 4.46,18.165 5.225,18.165 5.941,18.165 6.616,18.165 7.321,18.165 8.063,18.165 8.843,18.165 11.862,30.078 12.577,30.078 11.862,30.813 12.577,30.813 11.862,31.631 12.577,31.631 16.12,34.787 16.824,34.787 17.578,34.787 18.283,34.787 16.12,35.502 17.578,35.502 18.283,35.502 16.816,35.51 11.656,35.713 12.371,35.713 24.187,36.031 25.623,36.031 24.909,36.043 26.35,36.043 11.656,36.418 12.371,36.418 24.557,36.583 25.289,36.583 25.975,36.583 11.656,37.093 12.371,37.093 24.196,37.105 24.909,37.105 25.623,37.105 26.319,37.105 11.656,37.81 12.371,37.81 11.656,38.574 12.371,38.574 2.049,45.832 2.774,45.832 3.499,45.832 4.263,45.832 5,45.832 5.735,45.832 6.553,45.832 7.303,45.832 8.008,45.832 8.683,45.832 9.4,45.832 10.164,45.832 2.049,46.547 2.774,46.547 3.499,46.547 4.263,46.547 5,46.547 5.735,46.547 6.553,46.547 7.303,46.547 8.008,46.547 8.683,46.547 9.4,46.547 10.164,46.547
MillerClamp_BOT: R53.1 U5.25 | length 13.7
  Top Layer w0.254: U5.25@35.3,18.032 35.303,18.035 36.179,18.035 36.854,18.71 36.854,18.855 v1(36.901,18.902)
  Layer 2 w0.254: v1(36.901,18.902) 40.565,18.902 41.706,17.761 45.506,17.761 45.937,18.191 v1(45.968,18.191)
  Bottom Layer w0.254: v1(45.968,18.191) 45.968,17.379 46.173,17.174 46.985,17.174 R53.1@47.022,17.211
MillerClamp_TOP: R34.1 U4.25 | length 12
  Top Layer w0.254: U4.25@35.2,31.166 36.152,31.166 36.515,31.529 36.612,31.529 v1(36.659,31.576)
  Layer 2 w0.254: v1(36.659,31.576) 36.693,31.543 41.334,31.543 v1(41.368,31.509)
  Bottom Layer w0.254: v1@41.334,31.543 v1(41.368,31.509) ; v1@41.434,31.509 v1(41.368,31.509) ; R34.1@46.837,31.309 41.568,31.309 v1(41.368,31.509)
NetC5_2: C5.2 R1.1 U1.2 | length 8.7
  Top Layer w0.254: R1.1@18.421,42.543 19.153,42.543 19.302,42.692 19.302,42.731 19.737,43.166 22.902,43.166 23.117,42.951 C5.2@23.117,42.152 ; C5.2@23.117,41.989 23.98,41.989 24.317,41.651 25.778,41.651 U1.2@25.825,41.699
NetC6_1: C6.1 C7.1 NT1.1 R6.1 U1.9 | length 28.9
  Top Layer w0.254: C7.1@34.682,44.782 34.682,44.113 34.908,43.887 v1(34.908,43.82) ; U1.9@35.675,37.799 36.295,37.799 36.609,37.485 36.847,37.485 v1(36.894,37.438) ; C6.1@39.177,45.179 v1(40.118,45.179) 41.873,45.179 42.334,44.718 43.1,44.718 43.934,45.552 46.51,45.552 46.672,45.713 46.672,46.311 R6.1@46.626,46.356
  Layer 2 w0.254: v1(34.908,43.82) 36.506,43.82 ; v1(36.894,37.438) 36.941,37.485 37.124,37.485 38.285,38.646 38.285,42.04 36.506,43.82 ; v1(40.118,45.179) 38.759,43.82 36.506,43.82
  Bottom Layer w0.254: v1(36.894,37.438) 38.545,39.089 NT1.1@40.362,39.089
NetC6_2: C6.2 R6.2 R58.1 U1.15 | length 15
  Top Layer w0.254: U1.15@35.675,41.699 35.753,41.777 36.806,41.777 36.955,41.925 36.955,44.89 37.295,45.23 37.771,45.23 37.901,45.36 37.901,46.004 38.227,46.33 v1(39.952,46.33) R58.1@41.064,46.33 R58.1@41.374,46.021 ; v1(43.975,46.255) 44.924,46.255 R6.2@45.026,46.356
  Bottom Layer w0.254: v1(39.952,46.33) 39.99,46.293 43.937,46.293 v1(43.975,46.255)
NetC7_2: C7.2 R4.2 U1.16 | length 5.9
  Top Layer w0.254: U1.16@35.675,42.349 35.756,42.349 35.834,42.427 C7.2@35.834,44.782 35.834,45.713 36.078,45.957 v1(36.078,46.024)
  Bottom Layer w0.254: v1(36.078,46.024) 36.084,46.018 R4.2@36.084,44.008
NetC8_2: C8.2 R3.1 R5.2 U1.1 | length 7.1
  Top Layer w0.254: R3.1@20.466,44.386 22.718,44.386 R5.2@22.794,44.31 22.816,44.332 C8.2@24.909,44.332 24.909,43.593 25.289,43.213 25.289,42.427 25.367,42.349 U1.1@25.825,42.349
NetC18_2: C18.2 R8.1 U3.2 | length 9
  Top Layer w0.254: R8.1@18.171,6.476 18.196,6.476 19.001,7.281 21.172,7.281 22.084,6.369 22.602,6.369 C18.2@22.867,6.104 23.645,6.104 23.794,6.253 23.794,6.761 24.09,7.057 25.419,7.057 25.497,6.979 U3.2@25.575,7.057
NetC19_1: C19.1 C20.1 NT2.1 R14.1 U3.9 | length 24.5
  Top Layer w0.254: C20.1@35.012,10.14 34.864,10.288 v1(34.864,11.582) 36.278,11.582 37.119,10.741 37.119,10.283 37.392,10.01 39.294,10.01 39.591,10.307 41.691,10.307 41.864,10.134 41.864,9.659 R14.1@42.019,9.505 ; U3.9@35.425,3.157 35.503,3.079 36.46,3.079 v1(36.698,2.841)
  Layer 2 w0.254: v1(34.864,11.582) 34.864,4.675 v1(36.698,2.841)
  Bottom Layer w0.254: v1(36.698,2.841) 39.851,2.841 NT2.1@39.909,2.899
NetC19_2: C19.2 R10.1 R14.2 U3.15 | length 7.8
  Top Layer w0.254: U3.15@35.425,7.057 35.503,7.135 36.511,7.135 37.249,7.873 37.976,7.873 38.125,8.022 C19.2@38.125,8.71 38.901,8.71 v1(39.294,9.102) 39.686,9.495 40.409,9.495 R14.2@40.419,9.505
  Bottom Layer w0.254: v1(39.294,9.102) 39.754,9.563 40.428,9.563 R10.1@40.486,9.505
NetC20_2: C20.2 R12.2 U3.16 | length 4.5
  Top Layer w0.254: U3.16@35.425,7.707 36.024,7.707 36.102,7.785 v1(36.102,8.882) 36.102,10.079 C20.2@36.163,10.14
  Bottom Layer w0.254: R12.2@35.862,10.14 35.775,10.053 35.775,9.275 36.102,8.948 v1(36.102,8.882)
NetC21_2: C21.2 R11.1 R13.2 U3.1 | length 11.4
  Top Layer w0.254: R11.1@15.778,8.565 15.854,8.642 16.571,8.642 17.215,9.286 19.256,9.286 19.405,9.137 R13.2@19.405,8.437 ; R13.2@19.383,8.415 R13.2@19.405,8.437 ; U3.1@25.575,7.707 21.742,7.707 21.5,7.949 21.5,8.379 C21.2@21.442,8.437 R13.2@19.405,8.437
NetC25_2: C25.2 U4.26 | length 6.5
  Top Layer w0.254: U4.26@35.2,31.666 35.223,31.689 35.956,31.689 36.474,32.206 v1(36.474,32.975)
  Bottom Layer w0.254: v1(36.474,32.975) 36.92,33.421 39.523,33.421 39.686,33.584 39.686,34.213 C25.2@39.623,34.277
NetC26_2: C26.2 U4.21 | length 8.5
  Top Layer w0.254: U4.21@35.2,29.166 35.223,29.143 36.166,29.143 36.471,28.838 36.565,28.838 36.651,28.751 36.895,28.751 37.388,29.245 37.388,33.716 37.568,33.896 C26.2@38.746,33.896
NetC27_1: C27.1 R23.2 U4.5 | length 5.2
  Top Layer w0.254: R23.2@22.45,28.99 C27.1@22.45,30.933 24.138,30.933 24.405,30.666 U4.5@25.6,30.666
NetC28_1: C28.1 R22.2 U4.4 | length 6.2
  Top Layer w0.254: R22.2@22.45,34.816 22.45,32.873 23.512,32.873 24.089,32.296 24.089,31.683 24.606,31.166 U4.4@25.6,31.166
NetC44_2: C44.2 U5.26 | length 5.7
  Top Layer w0.254: U5.26@35.3,18.532 35.323,18.555 36.056,18.555 36.324,18.822 36.324,19.346 36.4,19.422 v1(36.4,19.489)
  Bottom Layer w0.254: v1(36.4,19.489) 36.41,19.479 39.192,19.479 39.341,19.627 39.341,19.933 39.689,20.281 C44.2@39.693,20.281
NetC45_2: C45.2 U5.21 | length 7.6
  Top Layer w0.254: U5.21@35.3,16.032 35.323,16.009 35.914,16.009 36.199,16.009 36.469,15.738 36.832,15.738 37.495,16.401 37.495,20.092 37.678,20.274 C45.2@38.712,20.274
NetC46_1: C46.1 R42.2 U5.5 | length 4.9
  Top Layer w0.254: R42.2@22.925,15.032 22.929,15.037 C46.1@22.929,16.975 22.994,17.039 23.662,17.039 24.154,17.532 U5.5@25.7,17.532
NetC47_1: C47.1 R41.2 U5.4 | length 5.1
  Top Layer w0.254: C47.1@22.93,18.916 23.659,18.916 24.543,18.032 U5.4@25.7,18.032 ; C47.1@22.929,18.916 R41.2@22.929,20.856
NetD1_1: D1.1 L1.2 U1.13 | length 7.4
  Top Layer w0.254: U1.13@35.675,40.399 35.745,40.469 36.78,40.469 v1(36.827,40.516) ; v1(36.95,39.078) 37.744,39.078 L1.2@37.924,39.259 38.248,38.935 38.907,38.935 39.143,38.699 D1.1@40.118,38.699
  Bottom Layer w0.254: v1(36.827,40.516) 36.423,40.516 36.096,40.189 36.096,39.248 36.265,39.078 v1(36.95,39.078)
NetD2_1: D2.1 L2.2 U3.13 | length 8.1
  Top Layer w0.254: U3.13@35.425,5.757 35.503,5.679 v1(36.87,5.679) ; v1(37.734,4.053) 37.734,3.181 L2.2@37.793,3.121 38.705,3.121 40.007,1.819 D2.1@40.967,1.819
  Bottom Layer w0.254: v1(36.87,5.679) 37.734,4.815 v1(37.734,4.053)
NetD3_1: D3.1 R18.1 | length 16.3
  Top Layer w0.254: v1(2.427,29.441) D3.1@2.427,30.946 ; v1(12.772,25.243) 14.25,25.243 14.596,24.897 R18.1@14.596,24.116
  Bottom Layer w0.254: v1(2.427,29.441) 3.435,28.432 8.146,28.432 11.336,25.243 v1(12.772,25.243)
NetD4_1: D4.1 R19.1 | length 25.6
  Top Layer w0.254: D4.1@5.135,30.946 5.135,29.682 6.1,28.717 8.449,28.717 10.741,26.425 v1(10.741,24.225) ; R19.1@14.895,10.736 14.9,10.741 v1(14.9,11.822)
  Bottom Layer w0.254: v1(10.741,24.225) 10.741,17.08 14.9,12.921 v1(14.9,11.822)
NetD5_1: D5.1 R17.1 | length 3.8
  Top Layer w0.254: D5.1@7.843,30.946 7.843,29.683 9.235,29.683 9.477,29.441 R17.1@10.233,29.441
NetD6_2: D6.2 R20.1 | length 1.5
  Top Layer w0.254: D6.2@16.436,18.655 16.904,18.655 17.073,18.486 R20.1@17.819,18.486
NetD7_2: D7.2 R21.1 | length 1.4
  Top Layer w0.254: D7.2@16.221,31.671 17.479,31.671 R21.1@17.604,31.546
NetD8_1: D8.1 D9.2
  other v1: 57.021,41.049 57.021,41.699
NetD8_2: D8.2 D18.1
  other v1: 58.745,36.263 59.288,36.263
NetD9_1: D9.1 J4.1 J4.2
NetD10_2: D10.2 R40.1 | length 1.8
  Top Layer w0.254: D10.2@49.809,36.935 51.514,36.935 R40.1@51.562,36.983
NetD13_1: D13.1 D14.2
  other v1: 57.4,5.107 57.4,5.757
NetD13_2: D13.2 D19.1
  other v1: 57.03,7.666 57.467,7.99
NetD14_1: D14.1 J8.1 J8.2
NetD15_2: D15.2 R57.1 | length 1.8
  Top Layer w0.254: D15.2@49.853,9.334 49.883,9.304 R57.1@51.627,9.304
NetD18_2: D18.2 R39.1 R40.2 | length 0.2
  Top Layer w0.254: R40.2@52.937,36.983 R40.2@52.922,36.983 R40.2@53.036,37.097
NetD19_2: D19.2 R56.1 R57.2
